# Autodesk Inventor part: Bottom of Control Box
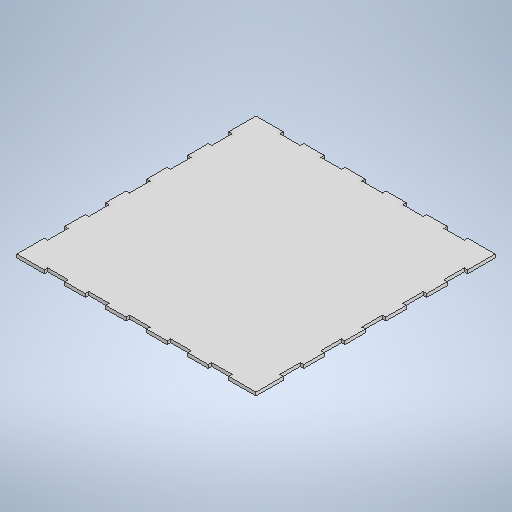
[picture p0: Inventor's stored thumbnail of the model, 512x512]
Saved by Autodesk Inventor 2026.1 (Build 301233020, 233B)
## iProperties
Created: 2026-11
Part Number: Bottom of Control Box
Material: Generic
Document SubType Name: Modeling
Designer: hp
Density: 1 g/cm^3
Appearance: Default
Author: hp
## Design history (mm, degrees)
sketch "Sketch1"
  geometry: L1 (0, 0)-(350, 0); L2 (350, 0)-(350, -350); L3 (350, -350)-(0, -350); L4 (0, -350)-(0, 0); L5 (190, -350)-(160, -350); L6 (160, -350)-(160, -345); L7 (160, -345)-(190, -345); L8 (190, -345)-(190, -350); L9 (130, -350)-(100, -350); L10 (100, -350)-(100, -345); L11 (100, -345)-(130, -345); L12 (130, -345)-(130, -350); L13 (70, -350)-(40, -350); L14 (40, -350)-(40, -345); L15 (40, -345)-(70, -345); L16 (70, -345)-(70, -350); L17 (250, -350)-(220, -350); L18 (220, -350)-(220, -345); L19 (220, -345)-(250, -345); L20 (250, -345)-(250, -350); L21 (190, -350)-(160, -350); L22 (160, -350)-(160, -345); L23 (160, -345)-(190, -345); L24 (190, -345)-(190, -350); L25 (130, -350)-(100, -350); L26 (100, -350)-(100, -345); L27 (100, -345)-(130, -345); L28 (130, -345)-(130, -350); L29 (310, -350)-(280, -350); L30 (280, -350)-(280, -345); L31 (280, -345)-(310, -345); L32 (310, -345)-(310, -350); L33 (250, -350)-(220, -350); L34 (220, -350)-(220, -345); L35 (220, -345)-(250, -345); L36 (250, -345)-(250, -350); L37 (190, -350)-(160, -350); L38 (160, -350)-(160, -345); L39 (160, -345)-(190, -345); L40 (190, -345)-(190, -350); L41 (350, -175)-(0, -175); L42 (175, 0)-(175, -350); L43 (250, -5)-(250, 0); L44 (250, 0)-(220, 0); L45 (220, 0)-(220, -5); L46 (220, -5)-(250, -5); L47 (190, -5)-(190, 0); L48 (190, 0)-(160, 0); L49 (160, 0)-(160, -5); L50 (160, -5)-(190, -5); L51 (70, -5)-(70, 0); L52 (100, 0)-(100, -5); L53 (100, -5)-(130, -5); L54 (130, 0)-(100, 0); L55 (130, -5)-(130, 0); L56 (70, 0)-(40, 0); L57 (40, 0)-(40, -5); L58 (40, -5)-(70, -5); L59 (280, -5)-(310, -5); L60 (310, -5)-(310, 0); L61 (310, 0)-(280, 0); L62 (280, 0)-(280, -5); L63 (190, -5)-(190, 0); L64 (250, 0)-(220, 0)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; 73 further points
  constraints: 300 end point, 90 symmetric about line, 6 midpoint, 6 parallel, 5 horizontal, 3 perpendicular, 2 vertical, 1 point on line, 144 other
  dimensions: "d0" = 350 distance of L2.end L3.end; "d1" = 350 distance of L1.end L2.end; "d5" = 30 distance of L6.end L7.end; "d6" = 5 distance of L5.end L6.end; "d10" = 60 distance of L5.start L9.start; "d13" = 60 distance of L5.start L17.start; "d16" = 5 distance of L81.end L80.end; "d17" = 30 distance of L80.end L79.end; "d20" = 60 distance of L79.end L83.end; "d23" = 60 distance of L79.end L91.end
extrude "Extrusion1" new body sketch "Sketch1" distance "d3" = 5; taper "d4" = 0 deg
body "Solid1"
node "Sketch Rectangular Pattern1" dims "d10" = 60, "d13" = 60
node "Sketch Rectangular Pattern2" dims "d20" = 60, "d23" = 60
